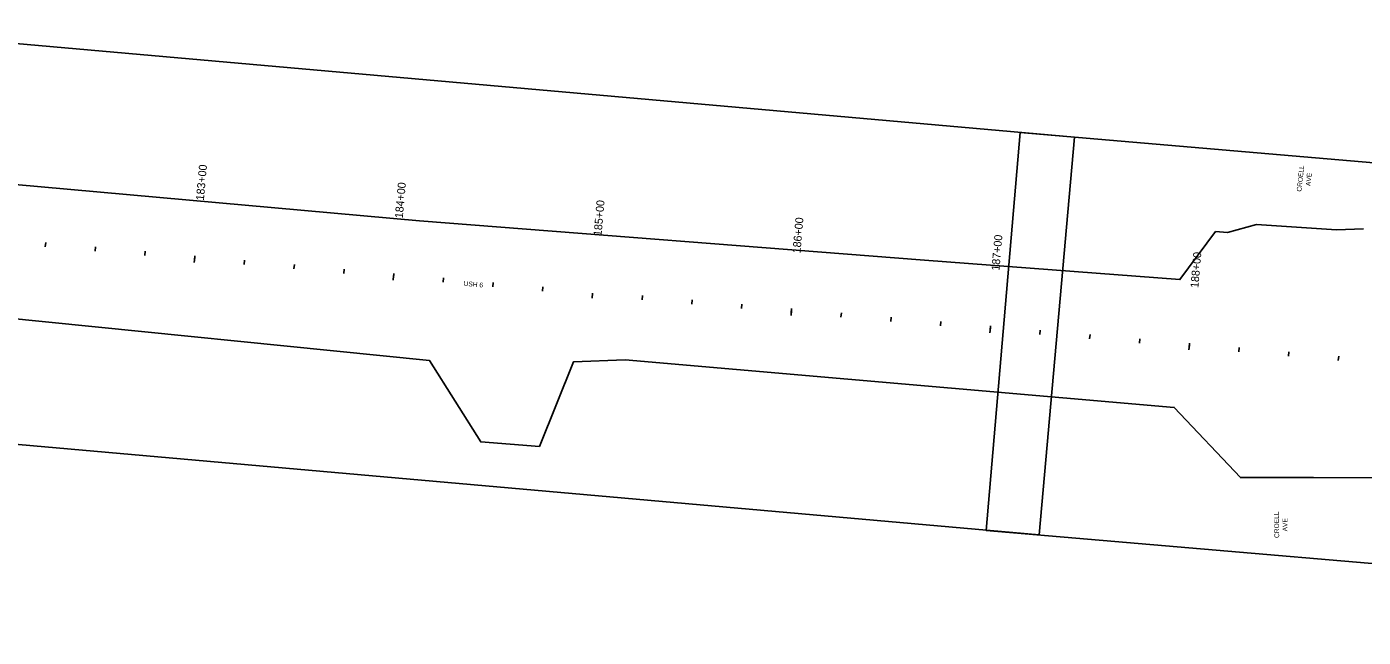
# Model space of a CAD drawing. Extents: x 20499876 to 20505320, y 7953544 to 7954108.
# Drawn here: x 20501924 to 20502593, y 7953684 to 7953990 of the extents above; entities that cross this region are included whole.
import ezdxf

# ---------------------------------------------------------------- set-up
doc = ezdxf.new("R2010")
doc.units = 0
for name, color, linetype in [('Alignment', 7, 'Continuous'), ('Curb', 7, 'Continuous'), ('Draft_0', 7, 'Continuous'), ('Draft_7', 7, 'Continuous'), ('UtilitiesBelowGround', 7, 'Continuous')]:
    doc.layers.add(name, color=color, linetype=linetype)

msp = doc.modelspace()

# ---------------------------------------------------------------- linework, layer by layer
at = {"layer": 'Alignment'}
for points in [[(20501823.68, 7953989.74), (20501806.03, 7953790.52), (20502430.58, 7953735.18), (20502448.23, 7953934.4)], [(20502421.05, 7953936.77), (20502403.97, 7953737.5), (20503028.68, 7953683.95), (20503045.76, 7953883.22)]]:
    msp.add_lwpolyline(points, close=True, dxfattribs=at)
at = {"layer": 'Curb'}
for p, q in [((20502007.59, 7953872.88), (20502007.78, 7953875.06)), ((20502107.19, 7953863.96), (20502107.38, 7953866.14)), ((20502206.9, 7953856.27), (20502206.68, 7953853.84)), ((20502306.41, 7953846.39), (20502306.6, 7953848.56)), ((20502406.04, 7953837.72), (20502406.23, 7953839.89)), ((20502505.66, 7953829.05), (20502505.85, 7953831.22))]:
    msp.add_line(p, q, dxfattribs=at)
at = {"layer": 'Draft_7'}
for p, q in [((20501932.88, 7953879.57), (20501933.08, 7953881.75)), ((20501957.79, 7953877.34), (20501957.98, 7953879.52)), ((20501982.69, 7953875.11), (20501982.88, 7953877.29)), ((20502007.7, 7953874.1), (20502007.48, 7953871.66)), ((20502032.49, 7953870.65), (20502032.68, 7953872.83)), ((20502057.39, 7953868.42), (20502057.58, 7953870.6)), ((20502082.29, 7953866.19), (20502082.48, 7953868.37)), ((20502107.3, 7953865.18), (20502107.08, 7953862.74)), ((20502132.09, 7953861.73), (20502132.28, 7953863.91)), ((20502156.99, 7953859.5), (20502157.18, 7953861.68)), ((20502181.89, 7953857.27), (20502182.08, 7953859.45)), ((20502206.9, 7953856.27), (20502206.68, 7953853.84)), ((20502231.7, 7953852.89), (20502231.89, 7953855.06)), ((20502256.6, 7953850.72), (20502256.79, 7953852.9)), ((20502281.51, 7953848.55), (20502281.7, 7953850.73)), ((20502306.52, 7953847.6), (20502306.31, 7953845.17)), ((20502331.32, 7953844.22), (20502331.51, 7953846.39)), ((20502356.23, 7953842.05), (20502356.41, 7953844.23)), ((20502381.13, 7953839.88), (20502381.32, 7953842.06)), ((20502406.14, 7953838.94), (20502405.93, 7953836.5)), ((20502430.94, 7953835.55), (20502431.13, 7953837.72)), ((20502455.85, 7953833.38), (20502456.04, 7953835.56)), ((20502480.75, 7953831.21), (20502480.94, 7953833.39)), ((20502505.77, 7953830.27), (20502505.55, 7953827.83)), ((20502530.57, 7953826.88), (20502530.76, 7953829.05)), ((20502555.47, 7953824.71), (20502555.66, 7953826.89)), ((20502580.38, 7953822.54), (20502580.57, 7953824.72))]:
    msp.add_line(p, q, dxfattribs=at)
at = {"layer": 'UtilitiesBelowGround'}
for points in [[(20500961.05, 7953985.49), (20501585.27, 7953936.81), (20501724.91, 7953925.27), (20501728.32, 7953926.51), (20501728.73, 7953931.44), (20501735.34, 7953931.05), (20501745.91, 7953953.5), (20501775.93, 7953950.79), (20501843.37, 7953917.33), (20502120.24, 7953892.49), (20502373.22, 7953872.83), (20502501.07, 7953863.11), (20502518.94, 7953887.24), (20502524.88, 7953886.71), (20502539.39, 7953890.66), (20502579.49, 7953887.98), (20502593.01, 7953888.5)], [(20502805.68, 7953763.59), (20502567.99, 7953764), (20502531.37, 7953763.95), (20502498.2, 7953799.08), (20502223.25, 7953822.85), (20502197.43, 7953821.94), (20502180.3, 7953779.46), (20502150.9, 7953781.82), (20502125.33, 7953822.5), (20501909.53, 7953844.31)]]:
    msp.add_lwpolyline(points, dxfattribs=at)

# ---------------------------------------------------------------- texts
at = {"layer": 'Curb'}
msp.add_text('185+00', height=4.008, rotation=85.02642, dxfattribs=at).set_placement((20502211.39, 7953884.77))
at = {"layer": 'Draft_0'}
for s, rotation, p in [('CROELL', 84.04085, (20502561.89, 7953907.04)), ('AVE', 84.04085, (20502566.41, 7953909.85)), ('USH 6', 355, (20502142.27, 7953859.98)), ('CROELL', 90.58727, (20502550.76, 7953733.68)), ('AVE', 90.58727, (20502554.93, 7953736.99))]:
    msp.add_text(s, height=2.4, rotation=rotation, dxfattribs=at).set_placement(p)
at = {"layer": 'Draft_7'}
for s, rotation, p in [('183+00', 84.88337, (20502012.26, 7953902.58)), ('184+00', 84.88337, (20502111.86, 7953893.66)), ('185+00', 85.02642, (20502211.39, 7953884.77)), ('186+00', 85.02642, (20502311.01, 7953876.1)), ('187+00', 85.02642, (20502410.63, 7953867.43)), ('188+00', 85.02642, (20502510.26, 7953858.76))]:
    msp.add_text(s, height=4.008, rotation=rotation, dxfattribs=at).set_placement(p)

doc.saveas('drawing.dxf')
